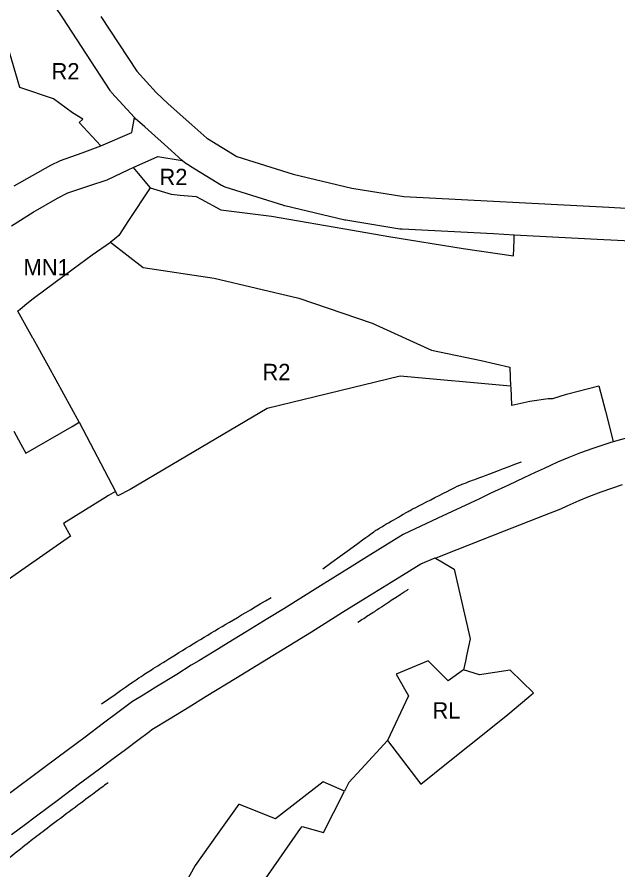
# Model space of a CAD drawing. Extents: x 7413438 to 7416393, y 5541665 to 5544118.
# Drawn here: x 7414832.1 to 7415052.1, y 5542969.5 to 5543282 of the extents above; entities that cross this region are included whole.
import ezdxf

# ---------------------------------------------------------------- set-up
doc = ezdxf.new("R2010")
doc.units = 0
for name, color, linetype in [('linie_rozgraniczajace', 7, 'Continuous'), ('linie_zabudowy_nieprzekraczalne', 7, 'Continuous'), ('oznaczenia_przeznaczen', 7, 'Continuous')]:
    doc.layers.add(name, color=color, linetype=linetype)

msp = doc.modelspace()

# ---------------------------------------------------------------- linework, layer by layer
at = {"layer": 'linie_rozgraniczajace'}
for p, q in [((7414848.81, 5543281.67), (7414846.08, 5543285.85)), ((7414866.12, 5543255.15), (7414848.81, 5543281.67)), ((7414862.77, 5543282.23), (7414875.9, 5543262.12)), ((7414833.08, 5543256.17), (7414826.4, 5543279.18)), ((7414875.9, 5543262.12), (7414883.01, 5543254.36)), ((7414845.46, 5543252.08), (7414833.08, 5543256.17)), ((7414866.3, 5543254.9), (7414866.12, 5543255.15)), ((7414866.54, 5543254.59), (7414866.3, 5543254.9)), ((7414866.72, 5543254.38), (7414866.54, 5543254.59)), ((7414852.43, 5543246.9), (7414845.46, 5543252.08)), ((7414875.06, 5543245.26), (7414866.72, 5543254.38)), ((7414883.01, 5543254.36), (7414887.37, 5543250.24)), ((7414887.37, 5543250.24), (7414896.13, 5543242.57)), ((7414856.11, 5543244.61), (7414852.43, 5543246.9)), ((7414874.07, 5543239.68), (7414875.06, 5543245.26)), ((7414875.62, 5543244.65), (7414875.06, 5543245.26)), ((7414854.87, 5543243.41), (7414856.11, 5543244.61)), ((7414862.82, 5543234.83), (7414854.87, 5543243.41)), ((7414876.19, 5543244.14), (7414875.62, 5543244.65)), ((7414878.84, 5543241.76), (7414876.19, 5543244.14)), ((7414896.13, 5543242.57), (7414901.57, 5543237.69)), ((7414862.82, 5543234.83), (7414874.07, 5543239.68)), ((7414888.47, 5543233.12), (7414878.84, 5543241.76)), ((7414901.57, 5543237.69), (7414901.86, 5543237.5)), ((7414901.86, 5543237.5), (7414912.59, 5543230.96)), ((7414855.91, 5543232.3), (7414862.82, 5543234.83)), ((7414892.59, 5543229.42), (7414888.47, 5543233.12)), ((7414844.4, 5543227.7), (7414847.94, 5543229.48)), ((7414847.94, 5543229.48), (7414855.91, 5543232.3)), ((7414874.65, 5543226.87), (7414883.57, 5543230.9)), ((7414883.57, 5543230.9), (7414892.59, 5543229.42)), ((7414912.59, 5543230.96), (7414933.15, 5543224.44)), ((7414837.77, 5543224.01), (7414844.4, 5543227.7)), ((7414872.97, 5543226.11), (7414874.65, 5543226.87)), ((7414874.65, 5543226.87), (7414876.46, 5543224.69)), ((7414893.52, 5543228.59), (7414892.59, 5543229.42)), ((7414895.45, 5543227.35), (7414893.52, 5543228.59)), ((7414895.55, 5543227.29), (7414895.45, 5543227.35)), ((7414895.56, 5543227.29), (7414895.55, 5543227.29)), ((7414906.96, 5543220.33), (7414895.56, 5543227.29)), ((7414831.03, 5543220.18), (7414837.77, 5543224.01)), ((7414865.13, 5543222.39), (7414872.97, 5543226.11)), ((7414876.46, 5543224.69), (7414880.77, 5543219.42)), ((7414933.15, 5543224.44), (7414954.64, 5543219.34)), ((7414850.66, 5543217.65), (7414858.34, 5543220.11)), ((7414858.34, 5543220.11), (7414865.13, 5543222.39)), ((7414907.3, 5543220.14), (7414906.96, 5543220.33)), ((7414907.65, 5543219.97), (7414907.3, 5543220.14)), ((7414846.9, 5543215.65), (7414850.66, 5543217.65)), ((7414880.77, 5543219.42), (7414872.85, 5543207.5)), ((7414880.77, 5543219.42), (7414888.46, 5543217.07)), ((7414888.46, 5543217.07), (7414891.83, 5543216.75)), ((7414908.02, 5543219.83), (7414907.65, 5543219.97)), ((7414908.27, 5543219.74), (7414908.02, 5543219.83)), ((7414929.73, 5543212.93), (7414908.27, 5543219.74)), ((7414954.64, 5543219.34), (7414973.67, 5543216.28)), ((7414838, 5543210.55), (7414846.9, 5543215.65)), ((7414891.83, 5543216.75), (7414891.75, 5543216.77)), ((7414891.75, 5543216.77), (7414897.66, 5543216.25)), ((7414897.66, 5543216.25), (7414899.47, 5543215.3)), ((7414899.47, 5543215.3), (7414906.69, 5543211.4)), ((7414973.67, 5543216.28), (7415048.71, 5543212.34)), ((7414906.69, 5543211.4), (7414925.24, 5543209.04)), ((7414929.85, 5543212.89), (7414929.73, 5543212.93)), ((7414930.16, 5543212.81), (7414929.85, 5543212.89)), ((7414952.08, 5543207.61), (7414930.16, 5543212.81)), ((7415048.71, 5543212.34), (7415072.06, 5543211.11)), ((7414829.99, 5543205.49), (7414838, 5543210.55)), ((7414925.24, 5543209.04), (7414954.92, 5543203.9)), ((7414952.15, 5543207.6), (7414952.08, 5543207.61)), ((7414952.52, 5543207.53), (7414952.15, 5543207.6)), ((7414872.85, 5543207.5), (7414869.41, 5543201.96)), ((7414972.24, 5543204.35), (7414952.52, 5543207.53)), ((7414869.41, 5543201.96), (7414867.18, 5543200.16)), ((7414954.92, 5543203.9), (7414968.19, 5543201.6)), ((7414968.19, 5543201.6), (7414995.48, 5543197.25)), ((7414972.26, 5543204.35), (7414972.24, 5543204.35)), ((7414972.65, 5543204.3), (7414972.26, 5543204.35)), ((7414973.04, 5543204.28), (7414972.65, 5543204.3)), ((7415006.55, 5543202.54), (7414973.04, 5543204.28)), ((7415014.14, 5543202.14), (7415006.55, 5543202.54)), ((7415014.09, 5543200.51), (7415014.14, 5543202.14)), ((7415044.53, 5543200.54), (7415014.14, 5543202.14)), ((7414859.58, 5543194.88), (7414866.24, 5543199.5)), ((7414867.18, 5543200.16), (7414866.24, 5543199.5)), ((7414866.24, 5543199.5), (7414878.24, 5543190.2)), ((7415013.97, 5543197.16), (7415014.09, 5543200.51)), ((7415062.72, 5543199.59), (7415044.53, 5543200.54)), ((7414995.48, 5543197.25), (7415013.92, 5543194.49)), ((7415013.92, 5543194.49), (7415013.97, 5543197.16)), ((7414852.66, 5543189.81), (7414859.58, 5543194.88)), ((7414838.43, 5543179.21), (7414852.66, 5543189.81)), ((7414878.24, 5543190.2), (7414904.27, 5543186.33)), ((7414904.27, 5543186.33), (7414935.3, 5543179.01)), ((7414833.07, 5543174.92), (7414834.97, 5543176.44)), ((7414834.97, 5543176.44), (7414837.44, 5543178.47)), ((7414837.44, 5543178.47), (7414838.43, 5543179.21)), ((7414935.3, 5543179.01), (7414962.13, 5543169.82)), ((7414832.33, 5543174.33), (7414833.07, 5543174.92)), ((7414832.39, 5543174.24), (7414832.33, 5543174.33)), ((7414837.87, 5543164.38), (7414832.39, 5543174.24)), ((7414962.13, 5543169.82), (7414983.82, 5543159.98)), ((7414837.94, 5543164.26), (7414837.87, 5543164.38)), ((7414843.6, 5543154.07), (7414837.94, 5543164.26)), ((7414983.82, 5543159.98), (7415002.06, 5543156.22)), ((7415002.06, 5543156.22), (7415012.53, 5543153.71)), ((7414854.83, 5543133.54), (7414843.6, 5543154.07)), ((7415012.53, 5543153.71), (7415012.51, 5543153.44)), ((7415012.51, 5543153.44), (7415012.81, 5543146.78)), ((7414972.33, 5543150.47), (7414923.65, 5543138.63)), ((7415012.81, 5543146.78), (7414972.33, 5543150.47)), ((7415012.81, 5543146.78), (7415012.83, 5543146.31)), ((7415012.83, 5543146.31), (7415012.83, 5543146.29)), ((7415012.83, 5543146.29), (7415013.13, 5543139.77)), ((7415033.28, 5543143.83), (7415045.12, 5543146.87)), ((7415045.12, 5543146.87), (7415047.54, 5543137.67)), ((7415019.84, 5543141.25), (7415026.53, 5543142.27)), ((7415026.53, 5543142.27), (7415028.3, 5543142.26)), ((7415028.3, 5543142.26), (7415033.28, 5543143.83)), ((7415013.13, 5543139.77), (7415013.2, 5543139.78)), ((7415013.2, 5543139.78), (7415019.84, 5543141.25)), ((7414923.65, 5543138.63), (7414888.73, 5543117.91)), ((7415047.54, 5543137.67), (7415049.39, 5543130.38)), ((7414852.24, 5543132.04), (7414854.83, 5543133.54)), ((7414854.83, 5543133.54), (7414868.1, 5543108.25)), ((7414830.96, 5543130.25), (7414833.49, 5543125.55)), ((7414835.3, 5543122.19), (7414852.24, 5543132.04)), ((7415049.39, 5543130.38), (7415050.38, 5543126.41)), ((7415050.38, 5543126.41), (7415049.17, 5543126.04)), ((7415058.7, 5543128.72), (7415050.38, 5543126.41)), ((7414833.49, 5543125.55), (7414835.3, 5543122.19)), ((7415042.86, 5543123.96), (7415038.34, 5543122.31)), ((7415045.79, 5543124.96), (7415042.86, 5543123.96)), ((7415049.17, 5543126.04), (7415045.79, 5543124.96)), ((7415034.08, 5543120.63), (7415029.95, 5543118.88)), ((7415038.34, 5543122.31), (7415034.08, 5543120.63)), ((7414888.73, 5543117.91), (7414873.53, 5543108.9)), ((7415027.38, 5543117.73), (7415025.06, 5543116.65)), ((7415029.95, 5543118.88), (7415027.38, 5543117.73)), ((7415021.84, 5543115.14), (7415017.59, 5543113.15)), ((7415025.06, 5543116.65), (7415021.84, 5543115.14)), ((7415017.59, 5543113.15), (7415011.97, 5543110.51)), ((7415045.95, 5543108.08), (7415053.82, 5543110.76)), ((7414868.1, 5543108.25), (7414865.54, 5543106.67)), ((7414868.97, 5543106.59), (7414868.1, 5543108.25)), ((7414873.55, 5543108.87), (7414868.97, 5543106.59)), ((7414873.53, 5543108.9), (7414873.55, 5543108.87)), ((7415011.97, 5543110.51), (7415005.6, 5543107.53)), ((7415041.39, 5543106.34), (7415045.95, 5543108.08)), ((7414864.27, 5543105.88), (7414849.07, 5543096.48)), ((7414865.54, 5543106.67), (7414864.27, 5543105.88)), ((7415001.36, 5543105.54), (7414986.17, 5543098.42)), ((7415005.6, 5543107.53), (7415001.36, 5543105.54)), ((7415033.54, 5543102.97), (7415037.89, 5543104.89)), ((7415037.89, 5543104.89), (7415041.39, 5543106.34)), ((7415025.24, 5543099.52), (7415031.14, 5543101.85)), ((7415031.14, 5543101.85), (7415033.54, 5543102.97)), ((7414986.17, 5543098.42), (7414973.43, 5543092.45)), ((7415010.54, 5543093.76), (7415025.24, 5543099.52)), ((7414849.07, 5543096.48), (7414851.64, 5543091.8)), ((7414973.43, 5543092.45), (7414971.86, 5543091.47)), ((7414988.59, 5543085.16), (7415010.54, 5543093.76)), ((7414851.64, 5543091.8), (7414740, 5543013.87)), ((7414971.86, 5543091.47), (7414966.79, 5543088.32)), ((7414966.79, 5543088.32), (7414959.05, 5543083.5)), ((7414959.05, 5543083.5), (7414953.86, 5543080.27)), ((7414979.88, 5543081.74), (7414985.15, 5543083.83)), ((7414985.15, 5543083.83), (7414985.27, 5543083.76)), ((7414985.27, 5543083.76), (7414988.59, 5543085.16)), ((7414985.27, 5543083.76), (7414987.56, 5543082.43)), ((7414953.86, 5543080.27), (7414943.17, 5543073.61)), ((7414969.01, 5543074.98), (7414979.88, 5543081.74)), ((7414987.56, 5543082.43), (7414992.11, 5543079.79)), ((7414992.11, 5543079.79), (7414997.94, 5543054.25)), ((7414943.17, 5543073.61), (7414929.72, 5543065.24)), ((7414959.55, 5543069.09), (7414969.01, 5543074.98)), ((7414951.29, 5543063.94), (7414959.55, 5543069.09)), ((7414929.72, 5543065.24), (7414923.91, 5543061.66)), ((7414939.84, 5543056.82), (7414951.29, 5543063.94)), ((7414923.91, 5543061.66), (7414916.02, 5543056.81)), ((7414916.02, 5543056.81), (7414909.38, 5543052.74)), ((7414919.79, 5543044.47), (7414939.84, 5543056.82)), ((7414909.38, 5543052.74), (7414904.24, 5543049.58)), ((7414997.94, 5543054.25), (7414996.78, 5543048.57)), ((7414904.24, 5543049.58), (7414898.65, 5543046.15)), ((7414996.78, 5543048.57), (7414996.26, 5543046.03)), ((7414898.65, 5543046.15), (7414895.82, 5543044.55)), ((7414982.61, 5543046.13), (7414970.88, 5543041.3)), ((7414989.94, 5543038.87), (7414982.61, 5543046.13)), ((7414996.26, 5543046.03), (7414995.6, 5543042.8)), ((7414895.82, 5543044.55), (7414890.58, 5543041.19)), ((7414912.25, 5543039.84), (7414919.79, 5543044.47)), ((7414995.6, 5543042.8), (7414989.94, 5543038.87)), ((7415001.42, 5543040.99), (7414995.6, 5543042.8)), ((7415012.6, 5543042.76), (7415001.42, 5543040.99)), ((7415021.19, 5543034.43), (7415012.6, 5543042.76)), ((7414890.58, 5543041.19), (7414882.92, 5543036.49)), ((7414901.37, 5543033.17), (7414912.25, 5543039.84)), ((7414970.88, 5543041.3), (7414975.37, 5543033.37)), ((7414882.92, 5543036.49), (7414878.26, 5543033.63)), ((7414878.26, 5543033.63), (7414874.38, 5543031.25)), ((7414895.16, 5543029.35), (7414901.37, 5543033.17)), ((7414975.37, 5543033.37), (7414967.75, 5543016.91)), ((7415011.81, 5543026.52), (7415019.51, 5543033.01)), ((7415019.51, 5543033.01), (7415021.19, 5543034.43)), ((7414874.38, 5543031.25), (7414869.42, 5543027.54)), ((7414869.42, 5543027.54), (7414863.7, 5543023.27)), ((7414887.85, 5543024.86), (7414895.16, 5543029.35)), ((7415003.69, 5543020.03), (7415011.81, 5543026.52)), ((7414863.7, 5543023.27), (7414856.99, 5543018.25)), ((7414881.45, 5543020.94), (7414887.85, 5543024.86)), ((7414876.34, 5543017.12), (7414880.59, 5543020.29)), ((7414880.59, 5543020.29), (7414881.45, 5543020.94)), ((7414856.99, 5543018.25), (7414850.41, 5543013.34)), ((7414871.76, 5543013.7), (7414876.34, 5543017.12)), ((7414990.6, 5543009.55), (7415003.69, 5543020.03)), ((7414967.75, 5543016.91), (7414958.06, 5543006.44)), ((7414967.75, 5543016.91), (7414976.37, 5543005.57)), ((7414967.75, 5543016.91), (7414967.75, 5543016.91)), ((7414850.41, 5543013.34), (7414842.32, 5543007.3)), ((7414867.3, 5543010.37), (7414871.76, 5543013.7)), ((7414862.29, 5543006.63), (7414867.3, 5543010.37)), ((7414979.87, 5543000.96), (7414990.6, 5543009.55)), ((7414842.32, 5543007.3), (7414837.45, 5543003.66)), ((7414854.5, 5543000.81), (7414862.29, 5543006.63)), ((7414958.06, 5543006.44), (7414953.52, 5543001.54)), ((7414976.37, 5543005.57), (7414979.87, 5543000.96)), ((7414837.45, 5543003.66), (7414827.02, 5542995.87)), ((7414944.21, 5543001.87), (7414926.69, 5542988.32)), ((7414951.94, 5542998.43), (7414944.21, 5543001.87)), ((7414953.52, 5543001.54), (7414951.94, 5542998.43)), ((7414847.27, 5542995.41), (7414854.5, 5543000.81)), ((7414947.91, 5542990.47), (7414951.94, 5542998.43)), ((7414843.49, 5542992.58), (7414847.27, 5542995.41)), ((7414838.72, 5542989.02), (7414843.49, 5542992.58)), ((7414913.23, 5542993.61), (7414905.4, 5542982.54)), ((7414913.31, 5542993.58), (7414913.23, 5542993.61)), ((7414913.51, 5542993.51), (7414913.31, 5542993.58)), ((7414926.69, 5542988.32), (7414913.51, 5542993.51)), ((7414913.51, 5542993.51), (7414913.51, 5542993.51)), ((7414835.16, 5542986.36), (7414838.72, 5542989.02)), ((7414944.28, 5542983.31), (7414947.91, 5542990.47)), ((7414830.03, 5542982.53), (7414835.16, 5542986.36)), ((7414930.07, 5542976.36), (7414935.91, 5542984.69)), ((7414935.91, 5542984.69), (7414936.44, 5542985.45)), ((7414936.44, 5542985.45), (7414944.28, 5542983.31)), ((7414905.4, 5542982.54), (7414897.33, 5542971.13)), ((7414920.11, 5542962.16), (7414930.07, 5542976.36)), ((7414897.33, 5542971.13), (7414893.99, 5542965.23))]:
    msp.add_line(p, q, dxfattribs=at)
at = {"layer": 'linie_zabudowy_nieprzekraczalne'}
for points, degree in [([(7414944.01, 5543079.88), (7414963.25, 5543093.83), (7414963.25, 5543093.83), (7414963.69, 5543094.13), (7414963.94, 5543094.28), (7414974.18, 5543100.25), (7414974.19, 5543100.25), (7414976.29, 5543101.47), (7414976.48, 5543101.58), (7414976.68, 5543101.69), (7414993.54, 5543110.26), (7414993.54, 5543110.26), (7414994.33, 5543110.59), (7415003.65, 5543114.11), (7415016.76, 5543119.1)], 3), ([(7414975.29, 5543072.26), (7414974.88, 5543072.02), (7414956.91, 5543060.2)], 2), ([(7414862.96, 5543030.42), (7414878.11, 5543040.89), (7414878.14, 5543040.9), (7414901.24, 5543055.43), (7414913.99, 5543062.71), (7414925.08, 5543069.39)], 3), ([(7414865.41, 5543001.51), (7414863.31, 5542999.93), (7414863.3, 5542999.93), (7414841.57, 5542983.67), (7414834.34, 5542978.05), (7414809.62, 5542958.24), (7414800.27, 5542951.67), (7414797.78, 5542948.59)], 3)]:
    msp.add_open_spline(points, degree=degree, dxfattribs=at)

# ---------------------------------------------------------------- texts
at = {"layer": 'oznaczenia_przeznaczen'}
for s, p in [('R2', (7414844.71, 5543259.14)), ('R2', (7414884.22, 5543220.42)), ('MN1', (7414834.46, 5543187.34)), ('R2', (7414921.93, 5543148.96)), ('RL', (7414984.19, 5543024.99))]:
    msp.add_text(s, height=6, dxfattribs=at).set_placement(p)

doc.saveas('drawing.dxf')
